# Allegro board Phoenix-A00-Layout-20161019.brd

Outline 244 x 258.83 mm; copper layers: TOP, L2_VCC, L3_GND, BOTTOM. Coordinates in mm from the lower left corner of the outline.
Outline path: 7.91,2.79 7.91,0 72.04,0 72.04,2.79 ; 125,10.37 125,10.13 ; 0,254.83 arc(1.17,257.66) 4,258.83 240,258.83 arc(242.83,257.66) 244,254.83 244,28.83 arc(242.83,26) 240,24.83 236,24.83 arc(235.29,24.53) 235,23.83 235,8.83 arc(234.41,7.41) 233,6.83 220.5,6.83 arc(219.79,7.12) 219.5,7.83 219.5,8.63 arc(219.21,9.33) 218.5,9.63 207.5,9.63 arc(206.79,9.33) 206.5,8.63 206.5,3.43 arc(205.91,2.01) 204.5,1.43 129,1.43 arc(126.17,2.6) 125,5.43 125,23.83 arc(124.71,24.53) 124,24.83 4,24.83 arc(1.17,26) 0,28.83 0,254.83

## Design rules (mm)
net group AUX_N: nets AUX_N EDP_AUX_DN_C
net group AUX_P: nets AUX_P EDP_AUX_DP_C
net group BRG_RXN: nets BRG_RXN PCH_HSON6
net group BRG_RXP: nets BRG_RXP PCH_HSOP6
net group BRG_TXN: nets BRG_TXN PCH_HSIN6
net group BRG_TXP: nets BRG_TXP PCH_HSIP6
net group BT_USB2_N6: nets BT_USB2_N6 U_USB6N_R
net group BT_USB2_N8: nets BT_USB2_N8 U_USB8N_R
net group BT_USB2_P6: nets BT_USB2_P6 U_USB6P_R
net group BT_USB2_P8: nets BT_USB2_P8 U_USB8P_R
net group CIIC_CLK: nets CIIC_SCL CIIC_SDA
net group CK_PE_100M_DMI: nets CK_PE_100M_DMI CK_PE_100M_DMI#
net group CLK_DEVICE_85OHM_4/4/15/20: nets CLKOUT_PCIE2 CLKOUT_PCIE2#
net group CLK_XTAL_24M_50OHM_4/15/20: nets XTAL_24M_IN XTAL_24M_OUT
net group CLKOUT_PCIE3: nets CLKOUT_PCIE3 N120560030
net group CLKOUT_PCIE3#: nets CLKOUT_PCIE3# N120560027
net group DMI_CPU_PCH_RXP2: nets DMI_CPU_PCH_RXN2 DMI_CPU_PCH_RXP2
net group DMI_PCH_CPU_RXP0: nets DMI_PCH_CPU_RXN0 DMI_PCH_CPU_RXP0
net group DMI_PCH_CPU_RXP2: nets DMI_PCH_CPU_RXN2 DMI_PCH_CPU_RXP2
net group EDP_LANE_DN2_C: nets EDP_LANE_DN2_C LANE0_N
net group EDP_LANE_DN3_C: nets EDP_LANE_DN3_C LANE1_N
net group EDP_LANE_DP2_C: nets EDP_LANE_DP2_C LANE0_P
net group EDP_LANE_DP3_C: nets EDP_LANE_DP3_C LANE1_P
net group EXP_A_TXN_0_C: nets EXP_A_TXN_0_C X_EXP_A_TX_C_DN0
net group EXP_A_TXN_1_C: nets EXP_A_TXN_1_C X_EXP_A_TX_C_DN1
net group EXP_A_TXN_2_C: nets EXP_A_TXN_2_C X_EXP_A_TX_C_DN2
net group EXP_A_TXN_3_C: nets EXP_A_TXN_3_C X_EXP_A_TX_C_DN3
net group EXP_A_TXN_4_C: nets EXP_A_TXN_4_C X_EXP_A_TX_C_DN4
net group EXP_A_TXN_5_C: nets EXP_A_TXN_5_C X_EXP_A_TX_C_DN5
net group EXP_A_TXN_6_C: nets EXP_A_TXN_6_C X_EXP_A_TX_C_DN6
net group EXP_A_TXN_7_C: nets EXP_A_TXN_7_C X_EXP_A_TX_C_DN7
net group EXP_A_TXN_8_C: nets EXP_A_TXN_8_C X_EXP_A_TX_C_DN8
net group EXP_A_TXN_9_C: nets EXP_A_TXN_9_C X_EXP_A_TX_C_DN9
net group EXP_A_TXN_10_C: nets EXP_A_TXN_10_C X_EXP_A_TX_C_DN10
net group EXP_A_TXN_11_C: nets EXP_A_TXN_11_C X_EXP_A_TX_C_DN11
net group EXP_A_TXN_12_C: nets EXP_A_TXN_12_C X_EXP_A_TX_C_DN12
net group EXP_A_TXN_13_C: nets EXP_A_TXN_13_C X_EXP_A_TX_C_DN13
net group EXP_A_TXN_14_C: nets EXP_A_TXN_14_C X_EXP_A_TX_C_DN14
net group EXP_A_TXN_15_C: nets EXP_A_TXN_15_C X_EXP_A_TX_C_DN15
net group EXP_A_TXP_0_C: nets EXP_A_TXP_0_C X_EXP_A_TX_C_DP0
net group EXP_A_TXP_1_C: nets EXP_A_TXP_1_C X_EXP_A_TX_C_DP1
net group EXP_A_TXP_2_C: nets EXP_A_TXP_2_C X_EXP_A_TX_C_DP2
net group EXP_A_TXP_3_C: nets EXP_A_TXP_3_C X_EXP_A_TX_C_DP3
net group EXP_A_TXP_4_C: nets EXP_A_TXP_4_C X_EXP_A_TX_C_DP4
net group EXP_A_TXP_5_C: nets EXP_A_TXP_5_C X_EXP_A_TX_C_DP5
net group EXP_A_TXP_6_C: nets EXP_A_TXP_6_C X_EXP_A_TX_C_DP6
net group EXP_A_TXP_7_C: nets EXP_A_TXP_7_C X_EXP_A_TX_C_DP7
net group EXP_A_TXP_8_C: nets EXP_A_TXP_8_C X_EXP_A_TX_C_DP8
net group EXP_A_TXP_9_C: nets EXP_A_TXP_9_C X_EXP_A_TX_C_DP9
net group EXP_A_TXP_10_C: nets EXP_A_TXP_10_C X_EXP_A_TX_C_DP10
net group EXP_A_TXP_11_C: nets EXP_A_TXP_11_C X_EXP_A_TX_C_DP11
net group EXP_A_TXP_12_C: nets EXP_A_TXP_12_C X_EXP_A_TX_C_DP12
net group EXP_A_TXP_13_C: nets EXP_A_TXP_13_C X_EXP_A_TX_C_DP13
net group EXP_A_TXP_14_C: nets EXP_A_TXP_14_C X_EXP_A_TX_C_DP14
net group EXP_A_TXP_15_C: nets EXP_A_TXP_15_C X_EXP_A_TX_C_DP15
net group F_USB2_N9: nets F_USB2_N9 USB_N9G_R
net group F_USB2_N10: nets F_USB2_N10 USB_N10G_R
net group F_USB2_P9: nets F_USB2_P9 USB_P9G_R
net group F_USB2_P10: nets F_USB2_P10 USB_P10G_R
net group F_USB3_N1: nets F_USB3_N1 U_USB1N_R
net group F_USB3_N2: nets F_USB3_N2 U_USB2N_R
net group F_USB3_P1: nets F_USB3_P1 U_USB1P_R
net group F_USB3_P2: nets F_USB3_P2 U_USB2P_R
net group FAN_PWM_4/12: nets O_CHAFAN_PWM O_CPUFAN_PWM
net group M2_SATA_RXN3_C: nets M2_SATA_RXN3_C SATA_RXN3
net group M2_SATA_RXP3_C: nets M2_SATA_RXP3_C SATA_RXP3
net group M2_SATA_TXN3_C: nets M2_SATA_TXN3_C SATA_TXN3
net group M2_SATA_TXP3_C: nets M2_SATA_TXP3_C SATA_TXP3
net group M_A_CK_D0: nets M_A_CK_DN0 M_A_CK_DP0
net group M_A_CK_D1: nets M_A_CK_DN1 M_A_CK_DP1
net group M_B_CK_D0: nets M_B_CK_DN0 M_B_CK_DP0
net group M_B_CK_D1: nets M_B_CK_DN1 M_B_CK_DP1
net group M_DQSA1: nets M_DQSA1 M_DQSA#1
net group M_DQSA2: nets M_DQSA2 M_DQSA#2
net group M_DQSA3: nets M_DQSA3 M_DQSA#3
net group M_DQSA4: nets M_DQSA4 M_DQSA#4
net group M_DQSA5: nets M_DQSA5 M_DQSA#5
net group M_DQSA6: nets M_DQSA6 M_DQSA#6
net group M_DQSB0: nets M_DQSB0 M_DQSB#0
net group M_DQSB1: nets M_DQSB1 M_DQSB#1
net group M_DQSB2: nets M_DQSB2 M_DQSB#2
net group M_DQSB3: nets M_DQSB3 M_DQSB#3
net group M_DQSB4: nets M_DQSB4 M_DQSB#4
net group M_DQSB5: nets M_DQSB5 M_DQSB#5
net group M_DQSB6: nets M_DQSB6 M_DQSB#6
net group M_DQSB7: nets M_DQSB7 M_DQSB#7
net group NIC_USB2_N4: nets NIC_USB2_N4 U_USB4N_R
net group NIC_USB2_N5: nets NIC_USB2_N5 U_USB5N_R
net group NIC_USB2_P4: nets NIC_USB2_P4 U_USB4P_R
net group NIC_USB2_P5: nets NIC_USB2_P5 U_USB5P_R
net group PCH_HSIN5: nets PCH_HSIN5 PCH_HSON5_C
net group PCH_HSIN5_C: nets PCH_HSIN5_C PCH_HSON5
net group PCH_HSIP5: nets PCH_HSIP5 PCH_HSOP5_C
net group PCH_HSIP5_C: nets PCH_HSIP5_C PCH_HSOP5
net group PCH_HSON7: nets PCH_HSON7 PCH_HSON7_C
net group PCH_HSOP7: nets PCH_HSOP7 PCH_HSOP7_C
net group PCIE_RCOMP: nets PCH_PCIE_RCOMP PCIE_RCOMP_R
net group R_USB3_N3: nets R_USB3_N3 U_USB3N_R
net group R_USB3_N7: nets R_USB3_N7 U_USB7N_R
net group R_USB3_P3: nets R_USB3_P3 U_USB3P_R
net group R_USB3_P7: nets R_USB3_P7 U_USB7P_R
net group RTC_4/15: nets ICH_RTCX1 ICH_RTCX2
net group SATA_RXN0: nets SATA_RXN0 SATA_RXN0_C
net group SATA_RXN1: nets SATA_RXN1 SATA_RXN1_C
net group SATA_RXN2: nets SATA_RXN2 SATA_RXN2_C
net group SATA_RXP0: nets SATA_RXP0 SATA_RXP0_C
net group SATA_RXP1: nets SATA_RXP1 SATA_RXP1_C
net group SATA_RXP2: nets SATA_RXP2 SATA_RXP2_C
net group SATA_TXN0: nets SATA_TXN0 SATA_TXN0_C
net group SATA_TXN1: nets SATA_TXN1 SATA_TXN1_C
net group SATA_TXN2: nets SATA_TXN2 SATA_TXN2_C
net group SATA_TXP0: nets SATA_TXP0 SATA_TXP0_C
net group SATA_TXP1: nets SATA_TXP1 SATA_TXP1_C
net group SATA_TXP2: nets SATA_TXP2 SATA_TXP2_C
net group USB3_RXDN1: nets USB3_RXDN1 USB3_RXDP1
net group USB3_TX1_PCH_DN_C: nets USB3_TX1_PCH_DN_C USB3_TXDN1
net group USB3_TX1_PCH_DP_C: nets USB3_TX1_PCH_DP_C USB3_TXDP1
net group USB3_TX2_PCH_DN_C: nets USB3_TX2_PCH_DN_C USB3_TXDN2
net group USB3_TX2_PCH_DP_C: nets USB3_TX2_PCH_DP_C USB3_TXDP2
net group USB3_TX3_PCH_DN_C: nets USB3_TX3_PCH_DN_C USB3_TXDN3
net group USB3_TX3_PCH_DP_C: nets USB3_TX3_PCH_DP_C USB3_TXDP3
net group USB3_TX4_PCH_DN_C: nets USB3_TX4_PCH_DN_C USB3_TXDN4
net group USB3_TX4_PCH_DP_C: nets USB3_TX4_PCH_DP_C USB3_TXDP4
net group ASYNCHRONOUS_50OHM_4/12: nets +DDR_PGOOD +VCCST_PWRGD APU_RST CPU_PCH_TRIGGER_OUT CPU_PCH_TRIGGER_OUT_R H_BPM#0 H_BPM#1 H_CATERR# H_PWRGOOD H_PWRGOOD_R H_THERMTRIP# PCH_CPU_TRIGGER_IN PCH_CPU_TRIGGER_IN_R PCH_ITP_PMODE PLTRST_IN_CPU# PMDOWN PMDOWN_CPU PMSYNC# PMSYNC#_R SIO_GP016 THERMTRIP#_PCH TP_BPM#2 TP_BPM#3 VCCST_PWRGD_1V VR_HOT VR_HOT_1V VRM_ALERT#_R VRM_SCLK_R VRM_SDIO_R XDP_CPU_HOOK6 XDP_CPU_HOOK6_R
net group AUDIO_10/10: nets A_HPOUT-L_R A_HPOUT-R_R A_JD1 A_JD2 A_LDO1_C A_LINE1-L_C A_LINE1-R_C A_LINE2_L_C A_LINE2_R_C A_MIC_C A_VREF AVDD2 DEPOP_LEFT DEPOP_LEFT_F DEPOP_RIGHT DEPOP_RIGHT_F HPOUT-JD HPOUT-L HPOUT-R LDO2_C LINE1-L LINE1-L_J LINE1-R LINE1-R_J LINE1-VREFO-L LINE1-VREFO-R LINE2-JD LINE2-L LINE2-R MIC2-VREFO
net group CLK_50OHM_4/15/20: nets CLKOUT_PCI0 LD_SIO_24M_CLOCKI_R PCH_24M_PCICLK SIO_24M_CLOCKI SIO_24M_CLOCKI_LPC SIO_24M_PCICLK
net group CLK_SRCCLKRQ_REQUEST_50OHM_4/15/20: nets CLK_REQ2_LAN_N CLKREQB EXP_A_PRSNT2# PCH_M2_SSD_CLKREQ_N TPM_TCM_CS V_GPI_VGA_CBL_DET# VGA_V_GPI_VGA_CBL_DET#_R
net group CRITICAL_50OHM_4/15: nets APS_PIN11 APS_PIN13 F_TP_XDP_RST FP_RST# GPP_A0 KBRST# N120811996 PCH_DPWROK PCH_DPWROK_C PCH_RSMRST# PCH_WAKE# PLTRST PLTRST_N PWRBTN_OUT# PWRBTN_OUT#_C PWRGD_140MS PWRGD_140MS_R SIO_GP026 SIO_RSMRST# TPM_RST_N VCORE_PG VCORE_PG_R WAKE#_L X16_X_RST_SLOT_PEG#_R X_PLTRST_PCIE_SLOT# X_RST_SLOT_PEG# X_RST_SLOT_PEG#_R XDP_FP_RST# XDP_PWRBTN_OUT# XDP_RSMRST#
net group DDR_A_ALERT_4/8: nets M_A_ALERT_N
net group DDR_A_CMD_35OHM_O8P5/6P5: nets M_A_ACT_N M_A_BA0 M_A_BA1 M_A_BA2 M_A_BG1 M_A_MA0 M_A_MA1 M_A_MA2 M_A_MA3 M_A_MA4 M_A_MA5 M_A_MA6 M_A_MA7 M_A_MA8 M_A_MA9 M_A_MA10 M_A_MA11 M_A_MA12 M_A_MA13 M_A_MA14 M_A_MA15 M_A_MA16 M_A_PAR
net group DDR_A_CTL_DIMM1_40OHM_O6P5/9P5: nets M_A_CKE0 M_A_CKE1 M_A_CS_N0 M_A_CS_N1 M_A_ODT0 M_A_ODT1
net group DDR_A_DATA0_40OHM_O6P5/18P5: nets M_DA0 M_DA1 M_DA2 M_DA3 M_DA4 M_DA5 M_DA6 M_DA7
net group DDR_A_DATA1_40OHM_O6P5/18P5: nets M_DA8 M_DA9 M_DA10 M_DA11 M_DA12 M_DA13 M_DA14 M_DA15
net group DDR_A_DATA2_40OHM_O6P5/18P5: nets M_DA16 M_DA17 M_DA18 M_DA19 M_DA20 M_DA21 M_DA22 M_DA23
net group DDR_A_DATA3_40OHM_O6P5/18P5: nets M_DA24 M_DA25 M_DA26 M_DA27 M_DA28 M_DA29 M_DA30 M_DA31
net group DDR_A_DATA4_40OHM_O6P5/18P5: nets M_DA32 M_DA33 M_DA34 M_DA35 M_DA36 M_DA37 M_DA38 M_DA39
net group DDR_A_DATA5_40OHM_O6P5/18P5: nets M_DA40 M_DA41 M_DA42 M_DA43 M_DA44 M_DA45 M_DA46 M_DA47
net group DDR_A_DATA6_40OHM_O6P5/18P5: nets M_DA48 M_DA49 M_DA50 M_DA51 M_DA52 M_DA53 M_DA54 M_DA55
net group DDR_A_DATA7_40OHM_O6P5/18P5: nets M_DA56 M_DA57 M_DA58 M_DA59 M_DA60 M_DA61 M_DA62 M_DA63
net group DDR_B_ALERT_4/8P5: nets M_B_ALERT_N
net group DDR_B_CMD_35OHM_I7/10P5: nets M_B_ACT_N M_B_BA0 M_B_BA1 M_B_BA2 M_B_BG1 M_B_MA0 M_B_MA1 M_B_MA2 M_B_MA3 M_B_MA4 M_B_MA5 M_B_MA6 M_B_MA7 M_B_MA8 M_B_MA9 M_B_MA10 M_B_MA11 M_B_MA12 M_B_MA13 M_B_MA14 M_B_MA15 M_B_MA16 M_B_PAR
net group DDR_B_CTL_DIMM2_40OHM_I5P5/14/14P25: nets M_B_CKE0 M_B_CKE1 M_B_CS_N0 M_B_CS_N1 M_B_ODT0 M_B_ODT1
net group DDR_B_DATA0_5P5/20: nets M_DB0 M_DB1 M_DB2 M_DB3 M_DB4 M_DB5 M_DB6 M_DB7
net group DDR_B_DATA1_5P5/20: nets M_DB8 M_DB9 M_DB10 M_DB11 M_DB12 M_DB13 M_DB14 M_DB15
net group DDR_B_DATA2_5P5/20: nets M_DB16 M_DB17 M_DB18 M_DB19 M_DB20 M_DB21 M_DB22 M_DB23
net group DDR_B_DATA3_5P5/20: nets M_DB24 M_DB25 M_DB26 M_DB27 M_DB28 M_DB29 M_DB30 M_DB31
net group DDR_B_DATA4_5P5/20: nets M_DB32 M_DB33 M_DB34 M_DB35 M_DB36 M_DB37 M_DB38 M_DB39
net group DDR_B_DATA5_5P5/20: nets M_DB40 M_DB41 M_DB42 M_DB43 M_DB44 M_DB45 M_DB46 M_DB47
net group DDR_B_DATA6_5P5/20: nets M_DB48 M_DB49 M_DB50 M_DB51 M_DB52 M_DB53 M_DB54 M_DB55
net group DDR_B_DATA7_5P5/20: nets M_DB56 M_DB57 M_DB58 M_DB59 M_DB60 M_DB61 M_DB62 M_DB63
net group DDR_RST_O4/8_I4/8P5: nets DDR4_DRAMRST# M_AB_RESET_N M_AB_RESET_N_R
net group DDR_VREF_O10/12: nets DIMM_DQ_CPU_VREF_A DIMMA_VREF_RC DIMMB_VREF_RC M_A_VREF M_B_VREF M_CA_VREF M_CA_VREF_RC M_DQ_VREF M_DQ_VREF_RC
net group DISPA_TBD: nets PCH_DISPA_BCLK PCH_DISPA_BCLK_R PCH_DISPA_SDI PCH_DISPA_SDI_R PCH_DISPA_SDO PCH_DISPA_SDO_R
net group DP_DATA/CLK_50OHM_4/12/15: nets HDMI_D41_PIN1 HDMI_D41_PIN2 HDMI_Q99_S HDMI_Q104_S
net group DPB_LANE_DN0_C: nets V_HDMI_TX2_DN
net group DPB_LANE_DN1_C: nets V_HDMI_TX1_DN
net group DPB_LANE_DN2_C: nets V_HDMI_TX0_DN
net group DPB_LANE_DN3_C: nets V_HDMI_CLK_DN
net group DPB_LANE_DP0_C: nets V_HDMI_TX2_DP
net group DPB_LANE_DP1_C: nets V_HDMI_TX1_DP
net group DPB_LANE_DP2_C: nets V_HDMI_TX0_DP
net group DPB_LANE_DP3_C: nets V_HDMI_CLK_DP
net group EDP_COMP_5/25: nets EDP_RCOMP
net group ESPI_50OHM_4/5: nets LAD2_SPIIRQ LPC_AD0 LPC_AD0_DEBUG LPC_AD0_TCM LPC_AD1 LPC_AD1_DEBUG LPC_AD1_TCM LPC_AD2 LPC_AD2_DEBUG LPC_AD2_TCM LPC_AD3 LPC_AD3_DEBUG LPC_AD3_TCM LPC_FRAME# LPC_FRAME#_DEBUG LPC_FRAME#_TCM PCH_LPC_AD0 PCH_LPC_AD1 PCH_LPC_AD2 PCH_LPC_AD3 PCH_LPC_FRAME# PLTRST#_SD_LPC PLTRST#_SD_LPC_DEBUG PLTRST#_SD_LPC_TCM SER_IRQ SUS_STAT_N TPM_SPIIRQ
net group HDA_TBD: nets A_QA3_G AUD_BITCLK AUD_BITCLK_R AUD_LINK_RESET# AUD_LINK_SDI0 AUD_LINK_SDIO_R AUD_SYNC FLASH_OVERRIDE# PCH_HDBCLK PCH_HDRST# PCH_HDSDO PCH_HDSYNC RSDATA_OUT
net group I2S_50OHM_4/10: nets O_AUD_PCSPKR_DET#
net group LAN_XTAL_4/15: nets XTAL_IN XTAL_OUT XTAL_OUT_R
net group OTHERS: nets 1P0V_PCH_EN 1P0V_PCH_FB 1P0V_PCH_FB_R 1P0V_PCH_PG 1P0V_PCH_SS 1P0V_PCH_TON 1P0V_PCH_VCCDSW 1P0V_PCH_VCCF24_FB_R 1P0V_PCH_VIN 1P0V_VCCAMPHYPLL_FB_R 1P0V_VCCAPLL_FB_R 3V_5V_PWROK 5V_DUAL_USB_EN_M 5V_SMART_USB_EN +1P0V_PCH_SN +1P0V_VCCST +1P2V_VDDQ_CS +1P2V_VDDQ_EN +1P2V_VDDQ_FB +1P2V_VDDQ_FB_R +1P2V_VDDQ_RF +1P2V_VDDQ_VCC +1P5V_VA +1P5V_VA_ADJ +3P3V_LPS_LDO +3P3V_PCIAUX +3P3V_SB_CS +3P3V_SB_FB +3P3V_SB_FB_R +3V_5V_EN +3V_5V_EN_3V +3V_5V_EN_3V_R +3V_5V_EN_5V +3V_5V_EN_R +3V_BATT +3V_VA +5V/3P3V_VIN +5V_3P3V_PG +5V_DDC +5V_HDMI +5V_PS2 +5V_SMART_USB +5V_USB_EN_L +5VAUX_CS +5VAUX_EN +5VAUX_FB +5VAUX_FB_R +5VAUX_LPS_LDO +5VAUX_VCLK +12V_SB +VCCGT +VCCIO_COMP_RC +VCCIO_DRV +VCCIO_DRV_R +VCCIO_FB +VCCIO_FB_R +VCCIO_FB_RC +VCCIO_FB_SENSE +VCCIO_SS +VCCIO_VCC +VCCRTC_SIO +VCCSA_CS +VCCSA_FB +VCCSA_FB_R +VCCSA_FB_VSS +VCCSA_RF +VCCSA_SN_20 +VCCSA_VCC_20 +VCCST_PWRGD_R +VCORE +VPP +VPP_BST +VPP_BST_RC +VPP_EN +VPP_FB +VPP_FB_R +VPP_FB_RC +VPP_LSN +VPP_PG +VPP_PVCC +VPP_VIN +VTT -12V -12V_COMP -12V_SWC -12V_SWE -12V_TCAP A_CBN A_CBP A_CPVEE A_EAPD_R A_FP_PRES# A_GND_C A_LDO3_C A_PCBEEP_C A_PVDD1 A_QA4_G A_SET A_SPEAKER_C A_SPKR_C A_VD33_STB APS_PIN1 APS_PIN2 APS_PIN3 APS_PIN4 APS_PIN5 APS_PIN6 AVCC33 B_ATX_PWROK BATT1 BATT_R_2 BRG_CLK_F3 BRG_REF0_PCIE BRG_REF1_PCIE BRG_REF01_PCIE_R BRG_TP_L10 BRG_TP_M11 BRG_TP_N12 BRG_VDD_15_COMB BRG_VDD_33_COMB BRG_VDD_33_COMBIO C_CLK_OUT0 C_CLK_OUT1 C_PCI_SL1 C_PCI_SL2 CFG0 CFG1 CFG2 CFG3 CFG4 CFG5 CFG6 CFG7 CFG8 CFG9 CFG10 CFG11 CFG12 CFG13 CFG14 CFG15 CFG16 CFG17 CFG18 CFG19 CFG_RCOMP CKBCLK CKBDATA CL_CLK_WLAN CL_DATA_WLAN CL_RST_WLAN# CL_SENCE# CLKRUN_EN CMCLR_2 CMSCLK CMSDATA CPU_FAN_+12V CPU_PRDY_N CPU_PREQ_N CPU_SELECT# D1_1 DDR_VTT_CNTL DP_HPD DPB_HPD_R DVCC_1P5V DVCC_1P5V_ADJ EAPD EAPD_R EDP_HPD_DDPE EDP_HPD_R ESPI_ALERT0 EVENT_A_R EVENT_B_R EXTARB_EN F_PCH_JTAG_TDI F_PCH_JTAG_TDO F_PCH_JTAG_TMS F_SPI_VCC FAN_CPU_PIN1 FAN_CPU_PWM FPNL_SATA_LED#_R GPIO0 GPIO2 GPIO4 GPIO_PEG SLOT_RESET GPP_A8 GPP_A13 GPP_B14 GPP_F17 GPP_F18 H_SKTOCC# H_TCK H_TDI H_TDO H_TMS H_TRST# H_TRST#_R HDMI_HPD HDMID_FET_SINK HS_DET# ISOLATEB JTAG_TCK JTAG_TRST# K_AD0 K_AD1 K_AD2 K_AD3 K_AD4 K_AD5 K_AD6 K_AD7 K_AD8 K_AD9 K_AD10 K_AD11 K_AD12 K_AD13 K_AD14 K_AD15 K_AD16 K_AD17 K_AD18 K_AD18_R K_AD19 K_AD20 K_AD21 K_AD22 K_AD23 K_AD24 K_AD25 K_AD26 K_AD27 K_AD28 K_AD29 K_AD30 K_AD31 K_C/BE#0 K_C/BE#1 K_C/BE#2 K_C/BE#3 K_DEVSEL# K_FRAME# K_GNT#0 K_GNT#1 K_INTA# K_INTB# K_INTC# K_INTD# K_IRDY# K_LOCK# K_PAR K_PCI_M66EN K_PCI_PME# K_PCIRST#_N K_PCIRST#_SLOT K_PERR# K_PME# K_REQ#0 K_REQ#1 K_SERR# K_STOP# K_TCK K_TCK1 K_TDI K_TDI1 K_TMS K_TMS1 K_TRDY# K_TRST K_TRST1 KBDCLK KBDDATA L_ACTLEDN L_ACTLEDN_R L_LINK100# L_LINK100#_R L_LINK1000# L_LINK1000#_R LAN_DISABLE# LAN_DISABLE#_R LAN_QL5_B LAN_QL5_C LAN_QL6_B LAN_QL7_G LAN_WAKE# LD_FP_RST#_R LD_LPC_DEBUG_PIN2 LD_LPC_DEBUG_PIN6 LDO_EN LED_M2_SSD_ACT_N LED_YELLOW_R M2_DEVSLP M2_PE_WAKE# M2_Q1_C M2_Q1A_B M2_Q2_B M.2_PEDET M.2_SSD_PEDET MSCLK MSDATA N120812085 N120812204 N120812265 N120812340 N120964019 N121283078 N121341151 N121341154 N121428079 N121488357 N121515008 N121515022 N121515024 N121515291 N121515335 O_+12VCOM O_-12VCOM O_A20GATE O_AUD_PCSPKR_DET#_SIO O_CPUFAN_PWM_R O_CTS1# O_CTS1#_R O_DCD1# O_DCD1#_R O_DSR1# O_DSR1#_R O_DTR1# O_DTR1#_R O_FIO_SATA_LED# O_FP_CBL_DET#_SIO O_GREEN# O_GREEN#_CTL O_GREEN#_R O_MB_REG_PG O_MB_REG_PG_R O_MEM_REG_PG O_MEM_REG_PG_R O_PCIAUX_CTRL O_PCIAUX_CTRL_R O_PWR2_PRSNT_R O_QO11_2 O_QO11_5 O_RI1# O_RI1#_R O_RTS1# O_RTS1#_R O_RXD1 O_RXD1_R O_SEN_CHAFAN O_SEN_CPUFAN O_SEN_CPUFAN_R O_SPEAKER O_SUS_3V_F_ON O_SUS_3V_ON O_SUS_3VON O_SUS_5VON O_TRST# O_TXD1 O_TXD1_R O_TXD1_R_C O_V5_ALW_MON O_V_IN O_YELLOW# O_YELLOW#_CTL O_YELLOW#_R OQ14_C PCH_AUD_MUTE PCH_FVS PCH_GPD0 PCH_GPD1 PCH_GPD4 PCH_GPD5 PCH_GPD6 PCH_JTAG_TCK PCH_OC#_0 PCH_OC#_1 PCH_OC#_2 PCH_OC#_3 PCH_OC#_4 PCH_OC#_5 PCH_PRDY_N PCH_PREQ_N PCH_STRAP_BBS PCH_STRAP_ESPI_EN PCH_STRAP_EXI_N PCH_STRAP_GPP_B18 PCH_STRAP_GPP_H12 PCH_STRAP_TLS PCI_CLKREQ# PCI_FBCLK PCI_REQ2# PCI_REQ3# PCI_REQ4# PCI_REQ5# PCIAUX_GATE_R PCIE_SLOT2_PRSNT_N PCIR PCLK66_SEL PD_USB2_VBUSSENSE PDB PECI_REQUEST POL1_SDA POL2_SCL PQ7_G PQ7_G_R PQ9_G PQ16_D1 PQ18A_BASE PQ18B_BASE PQ19_D1 PQ21_G1 PQ21B_D1 PQ24B_D PQ24B_G PQ42A_D1 PQ42A_G1 PQ47_C PQ47_G PQ49B_GATE PQ53_G1 PQ54_G PQ55_G PQ55B_D PQ57A_D1 PQ57B_G2 PQ71_D1 PQ79_C PQ79_G PU21_Y PV_RTCEXT QS10_B QS10_E REFCLK_SEL REGOUT RGB_IMPEDANCE RING2 RING2_J RTK_RSET_R S_GPI_BRD_REV0 S_GPI_BRD_REV1 S_MFG_MODE_OR S_PCIAUX_GATE S_PME# S_PSWD_CLR S_SLP_S5#_SIO S_USB3_HDR_DET# SATA_LED# SATAGP0 SATAGP0_R SATAGP1 SATAGP2 SATAGP3 SATAGP4 SATAGP5 SATAGP5_R SATAGP6 SATAGP6_R SATAGP7 SD4_WAKE SER_SENCE# SERIRQ SERVICE_MODE_1 SIO_24M_TCM SIO_CAP1 SIO_CLOCKI SIO_GP004 SIO_GP010 SIO_GP011 SIO_GP071 SIO_PCIAUX_G SIO_PECI_R SIO_PWRGD SIO_QO1A_B SIO_QO1B_B SIO_QO2A_B SIO_QO2B_B SIO_QO3A_B SIO_QO3B_B SIO_QO4A_B SIO_QO4B_B SIO_QO5A_B SIO_QO5B_B SIO_SLP_S4#_R SIO_SLP_SUS SIO_SLP_WLAN_N_R SLEEVE SLEEVE_J SLP_A# SLP_S0_N SLP_S3# SLP_S4# SLP_S5# SLP_SUS# SLP_SUS#_PCH SLP_SUS_FET_R SLP_WLAN_N SPI_VDD1 SPI_VDD3 SPKR SSD_SATA_DEVSLP3 SUS_PWR_ACK# SUS_WARN# SUSCLK_PCH SUSCLK_SIO SW_TPM SYS_FAN_+12V SYSTEM_FAN22 SYSTEM_FAN23 TCM_SIO_24M_TCM_R TCM_SIO_CLOCKI_R TCM_UF3_PIN2 TMIN_SHIFT TP_AJ24 TP_AK21 TP_AK22 TP_APU_RSVD_AC37 TP_APU_RSVD_AU9 TP_APU_RSVD_AU10 TP_APU_RSVD_AU39 TP_APU_RSVD_AU40 TP_APU_RSVD_AV39 TP_APU_RSVD_AW38 TP_APU_RSVD_B39 TP_APU_RSVD_C40 TP_APU_RSVD_D15 TP_APU_RSVD_J11 TP_APU_RSVD_J13 TP_APU_RSVD_J14 TP_APU_RSVD_J15 TP_APU_RSVD_J17 TP_APU_RSVD_J19 TP_APU_RSVD_K10 TP_APU_RSVD_K11 TP_APU_RSVD_K12 TP_APU_RSVD_K13 TP_APU_RSVD_L10 TP_APU_RSVD_L12 TP_APU_RSVD_TP_AV1 TP_APU_RSVD_TP_AW2 TP_APU_RSVD_TP_H11 TP_APU_RSVD_TP_H12 TP_APU_RSVD_TP_J7 TP_APU_RSVD_TP_J8 TP_APU_RSVD_TP_K8 TP_APU_RSVD_TP_L8 TP_APU_ZVM# TP_EDP_DISP TP_F36 TP_F37 TP_GPP_D4_ISH_I2C2_SDA TP_GPP_D14_ISH_UART0_TXD TP_GPP_D18_DMIC_DATA1 TP_GPP_D19_DMIC_CLK0 TP_GPP_H15_SML3ALERT_N TP_GPP_H18_SML4ALERT_N TP_PCH_B19 TP_PCH_B20 TP_PCH_C19 TP_PCH_C20 TP_PCH_E17 TP_PCH_G17 TP_PCH_K17 TP_PCH_L17 TP_PCH_RSVD0 TP_PCH_RSVD1 TP_PCH_RSVD2 TP_PCH_RSVD3 TP_PCH_RSVD4 TP_PCH_RSVD5 TP_PCH_RSVD6 TP_PCH_RSVD7 TP_PCH_RSVD8 TP_PCH_RSVD9 TP_PCH_RSVD10 TP_PCH_RSVD11 TP_PCH_RSVD12 TP_PCH_RSVD13 TP_PCH_RSVD14 TP_PCH_RSVD15 TP_PCH_RSVD16 TP_PCH_RSVD17 TP_PCH_RSVD18 TP_PCH_TP4 TP_PCH_TP5 TP_SIO_GP054 TPM_BADD TPM_PP TPM_QF1_G TPM_SERIRQ TPM_VDD2 UEFI_S USB2_ID USBPWR0_F_50 USBPWR1_F_50 USBPWR4_F_50 USBPWR5_F_50 V_BLUE_R V_GREEN_R V_HSYNC_5V_R V_RED_R V_VSYNC_5V_R VCC_AUD VCC_OBS_AB VCC_OBS_CD VCC_OBS_R VCC_OPC_R VCCEOPIO_R VCCGT_HSN_1 VCCGT_HSN_2 VCCGTX2_L31 VCCHDA_BA15 VCCIO_EN VCCIO_PG VCCIO_SENSE VCCK_V12 VCCOPC_R VCCPGPPA VCCPGPPCD_BA45 VCCPLL_OC_R VCCPRIM_AL22 VCCPRIM_BE3 VCCSA_SENSE VCCSOKET VCCSPI VCORE_EN VCORE_EN_FREQUENCE VCORE_HSN_1 VCORE_HSN_2 VCORE_HSN_3 VCT VDD10 VDD_DAC_33 VDDA_1P5V VDDA_3P3V VDDQ_SN VDDQ_VTT_REFEN VGA_5V_DDC_R VGA_BLUE_P VGA_GREEN_P VGA_HSYNC VGA_PRX_PIN28 VGA_RED_P VGA_RGB_CV VGA_SCL VGA_SDA VGA_VSYNC VGAPWR_F_20 VGT_VCC1_20 VGT_VCC2_20 VISACH1_D2_PCH_GPP_E_5 VISACH1_D2_PCH_GPP_E_6 VPP_PG VRALERT_N VREF_RC VREG_PD33 VRM_SETA1 VRM_SN1_20 VRM_SN2_20 VRM_SN3_20 VRM_VCC VRM_VCC1_20 VRM_VCC2_20 VRM_VCC3_20 VSS_AB10 VSS_AB11 VSSSAIO_SENSE VSSSOKET WAKE_SLOT1_N WAKE_SLOT_M2_N X1_TCLK X1_TDI X1_TRST X16_RST_SLOT_PEG# X16_RST_SLOT_PEG#_R X16_TCLK X16_TDI X16_TMS X16_TRST X_PCI1_ACK64#_R X_PCI1_K_AD17_R X_PCI1_REQ64#_R X_PCI1_SMBCLK_R X_PCI1_SMBDATA_R X_PCI_ACK64#_B60 X_PCI_REQ64#_A60 X_PCI_SMBCLK_R X_PCI_SMBDATA_R XDP_HOOK2 XDP_PCH_JTAGX XDP_PRESENT#_CPU
net group PECI_50OHM_4/18: nets H_PECI H_PECI_C PCH_PECI_R
net group PEG_RCOMP_5/15: nets PEGICOMP_MCP
net group PHASE_20: nets +1P2V_VDDQ_BOOT_20 +1P2V_VDDQ_BOOT_R20 +1P2V_VDDQ_LG_30 +1P2V_VDDQ_UG_20 +1P2V_VDDQ_UG_R20 +3P3V_SB_BOOT_20 +3P3V_SB_BOOTR_20 +5VAUX_BOOT_20 +5VAUX_BOOTR_20 PQ11_GATE PQ11_GATE_R PQ23_GATE VGT_BOOT1_20 VGT_BOOT1_RC_20 VGT_BOOT2_20 VGT_BOOT2_RC_20 VGT_LG1_R_30 VGT_LG2_R_30 VGT_SN1_20 VGT_SN2_20 VGT_UG1_20 VGT_UG1_R_20 VGT_UG2_20 VGT_UG2_R_20 VRM_BOOT1_20 VRM_BOOT1_RC_20 VRM_BOOT2_20 VRM_BOOT2_RC_20 VRM_BOOT3_20 VRM_BOOT3_RC_20 VRM_LG1_R_30 VRM_LG2_R_30 VRM_LG3_R_30 VRM_UG1_20 VRM_UG1_R_20 VRM_UG2_20 VRM_UG2_R_20 VRM_UG3_20 VRM_UG3_R_21
net group PHASE_25: nets 1P0V_PCH_BOOT_25 +3P3V_SB_LG_25 +3P3V_SB_PHASE_R +3P3V_SB_UG25 +3P3V_SB_UGR_25 +5VAUX_LG_25 +5VAUX_PHASE_R +5VAUX_UG_25 +5VAUX_UGR_25 +VCCSA_BOOT_25 +VCCSA_BOOT_R25 +VCCSA_HG_25 +VCCSA_HG_R_25 +VCCSA_LG_25
net group PWM_8: nets COMP_R COMPA_R CS1+_RT3607 CS1-_RT3607 CS2+_RT3607 CS2-_RT3607 CS3+_RT3607 CS3-_RT3607 CS4-_RT3607 GT1+_RT3607 GT1-_RT3607 GT2+_RT3607 GT2-_RT3607 GT3-_RT3607 GT_COMPA GT_FBA GT_VSENA IMON IMON_L IMON_R IMONA IMONA_L IMONA_R RGNDA TONSET_R TONSETA TONSETA_R TSEN TSEN_R1 TSEN_R2 TSENA TSENA_R1 TSENA_R2 VCCGT_PWM1_10 VCCGT_PWM2_10 VCCGT_SENSE VREF_R VREF_RA VRM_COMP VRM_DVD VRM_FB VRM_IBIAS VRM_PWM1_10 VRM_PWM2_10 VRM_PWM3_10 VRM_RGND VRM_SET1 VRM_SET1_R VRM_SET1_RR VRM_SET2 VRM_SET2_R VRM_SET2_RR VRM_SET3 VRM_SET3_R VRM_SET3_RR VRM_SETA1_R VRM_SETA1_RR VRM_SETA2 VRM_SETA2_R VRM_SETA2_RR VRM_TON VRM_VREF VRM_VSEN VSSGT_SENSE
net group RTCRST_4/15: nets APS_PIN9 ICH_RTCRST# O_PSON#
net group SPI_50OHM_4/5: nets CS2_LFRAM# F_SPI_HOLD# F_SPI_MISO_R F_SPI_MISO_TPM F_SPI_MOSI_PRI_SEC_FLSH_R F_SPI_MOSI_PRI_SEC_FLSH_TPM F_SPI_WP# LAD0_MISO LAD1_MOSI SPI_CS# SPI_IO2 SPI_IO3 SPI_MISO SPI_MOSI SPI_TPM_CS2# TPM_CS2_LFRAM#_R XDP_PRESENT#_R XDP_SPI_MOSI
net group SPI_CLK_50OHM_4/15: nets F_SPI_CLK_PRI_SEC_FLSH_R F_SPI_CLK_PRI_SEC_FLSH_TPM SPI_SCK TPM_CLK
net group SRTCRST#_4/15: nets SRTCRST#_ICH
net group SVID_50OHM_4/15: nets VIDALERT_# VIDSCLK VIDSOUT VRM_ALERT# VRM_SCLK VRM_SDIO
net group UART2_50OHM_4/5: nets RING#
net group USB_COMP_50OHM_4/15: nets A_USB2_COMP
net group XCLK_BIASREF_4/15/20: nets XCLK_RCOMP

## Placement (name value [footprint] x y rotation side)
APS/PETS  Header_2X7_GF_Black  [H2X7MZ]  10.19 185.8 180 top
ATX_CPU  PWR_2X2_4.2_Nature  [PWR4NWP1]  223.83 204.15 270 top
ATX_SYS  PWR_2X4_4.2_100u_Nature  [PWR_2X4_165_PEGL_WL496]  34.08 29.9 180 top
AUX_PWR1  LED_Yellow  [D0603_H31]  11.72 34.54 180 top
BATTERY  Battery Holder_H  [BAT2_200D223-1]  186.95 50.41 180 top
BH1  74LVC1G17SE-7  [SOT353_5]  29.37 116.46 270 top
BRIDGE  XIO2001ZGU  [BGA_169_472X472]  59.6 196.6 180 top
C1  1uF_X5R_6.3V  [C0402]  170.54 84.51 90 top
C2  1uF_X5R_6.3V  [C0402]  167.6 84.53 90 top
C3  1uF_X5R_6.3V  [C0402]  108.36 84.45 0 top
C5  1uF_X5R_6.3V  [C0402]  147.51 84.53 90 top
C6  100nF_X5R_10V  [C0402]  117.64 84.45 180 top
C7  100nF_X5R_10V  [C0402]  147.35 94.23 270 top
C8  100nF_X5R_10V  [C0402]  145.73 84.53 270 top
C9  100nF_X5R_10V  [C0402]  152.18 95.5 270 top
C19  100nF_X5R_10V  [C0402]  149.13 94.23 270 top
C20  4.7uF_X5R_6.3V  [C0603]  155.61 73.66 180 top
C21  100nF_X5R_6.3V  [C0402]  159.29 72.77 0 top
C22  100nF_X7R_10V  [C0402]  99.73 93.09 0 top
C23  100nF_X7R_10V  [C0402]  99.73 94.11 0 top
C24  2.2uF_X5R_6.3V  [C0402]  107.86 75.82 180 top
C25  100nF_X7R_16V  [C0402]  109.89 75.82 0 top
C48  1uF_X5R_6.3V  [C0402]  161.7 84.48 90 top
C49  1uF_X5R_6.3V  [C0402]  208.31 84.58 180 top
C50  1uF_X5R_6.3V  [C0402]  181.41 84.53 90 top
C51  1uF_X5R_6.3V  [C0402]  217.58 84.33 180 top
C52  100nF_X5R_10V  [C0402]  167.93 94.74 270 top
C53  100nF_X5R_10V  [C0402]  162.97 94.62 270 top
C54  100nF_X5R_10V  [C0402]  159.8 94.62 270 top
C55  100nF_X5R_10V  [C0402]  172.25 75.31 90 top
C56  100nF_X5R_10V  [C0402]  149.77 84.45 180 top
C57  22uF_X5R_6.3V  [C0805]  188.37 84.45 180 top
C58  22uF_X5R_6.3V  [C0805]  212.89 84.58 180 top
C59  22uF_X5R_6.3V  [C0805]  175.04 95.63 0 top
C60  22uF_X5R_6.3V  [C0805]  175.04 93.98 0 top
C61  22uF_X5R_6.3V  [C0805]  174.66 84.58 0 top
C62  4.7uF_X5R_6.3V  [C0603]  156.93 84.56 180 top
C63  100nF_X5R_6.3V  [C0402]  159.29 84.71 0 top
C64  100nF_X7R_10V  [C0402]  98.33 84.96 0 top
C65  100nF_X7R_10V  [C0402]  98.33 84.07 0 top
C66  2.2uF_X5R_6.3V  [C0402]  101.25 84.07 0 top
C67  100nF_X7R_16V  [C0402]  101.25 84.96 0 top
C68  2.2uF_X5R_6.3V  [C0402]  221.78 75.44 270 top
C69  100nF_X7R_16V  [C0402]  222.79 75.44 270 top
C70  100nF_X7R_10V  [C0402]  119.3 193.04 90 top
C71  100nF_X7R_10V  [C0402]  216.31 75.44 270 top
C72  4.7uF_X5R_6.3V  [C0603]  220.63 75.06 270 top
C73  22nF_X7R_16V  [C0402]  224.82 75.44 90 top
C74  100nF_X7R_10V  [C0402]  130.14 195.66 90 top
C75  100nF_X7R_10V  [C0402]  130.88 207.39 90 top
C228  1uF_X5R_16V  [C0603]  170.72 56.26 0 top
C379  10nF_X7R_25V  [C0402]  186.22 234.19 180 top
C383  10nF_X7R_25V  [C0402]  181.9 224.28 0 top
C386  10nF_X7R_25V  [C0402]  178.47 234.06 180 top
C409  100nF_X7R_16V  [C0402]  159.55 238.96 270 top
C410  150pF_NPO_25V  [C0402]  151.04 235.33 270 top
C411  150pF_NPO_25V  [C0402]  151.04 237.36 270 top
C412  150pF_NPO_25V  [C0402]  146.46 235.2 270 top
C413  150pF_NPO_25V  [C0402]  146.46 237.24 270 top
C414  100pF_NPO_50V  [C0402]  158.53 238.94 270 top
C415  10nF_X7R_25V  [C0402]  160.57 238.96 90 top
C531  100nF_X7R_16V  [C0402]  225.54 253.11 0 top
C558  470pF_X7R_50V  [C0402]  219.45 242.09 270 top
C766  100nF_X7R_16V  [C0402]  172.12 53.72 0 top
C1629  100pF_X7R_50V  [C0402]  31.28 118.75 270 top
C1630  1uF_X5R_6.3V  [C0402]  42.71 130.56 180 top
C1639  1uF_X5R_6.3V  [C0603]  39.78 130.81 0 top
C1640  12pF_NPO_50V  [C0402]  40.04 132.21 180 top
C1641  12pF_NPO_50V  [C0402]  40.04 133.22 180 top
C1642  27pF_NPO_50V  [C0402]  74.58 132.59 315 top
C1643  27pF_NPO_50V  [C0402]  74.46 133.99 0 top
C1644  100nF_X7R_10V  [C0402]  43.34 119.63 90 top
C1645  1uF_X5R_6.3V  [C0402]  42.32 119.63 90 top
C1646  1uF_X5R_6.3V  [C0402]  62.14 142.11 180 top
C1647  1uF_X5R_6.3V  [C0402]  40.93 121.28 180 top
C1648  100nF_X7R_10V  [C0402]  40.04 111 0 top
C1649  100nF_X7R_10V  [C0402]  40.04 110.11 0 top
C1654  47uF_X5R_6.3V  [C0805]  73.95 111.73 0 top
C1655  47uF_X5R_6.3V  [C0805]  73.95 110.08 0 top
C1656  47uF_X5R_6.3V  [C0805]  43.59 109.35 270 top
C1657  47uF_X5R_6.3V  [C0805]  41.94 109.35 270 top
C1660  22uF_X5R_6.3V  [C0805_H37]  56.68 147.57 0 top
C1661  22uF_X5R_6.3V  [C0805_H37]  56.68 145.8 0 top
C1664  22uF_X5R_6.3V  [C0805_H37]  67.85 110.11 180 top
C1665  22uF_X5R_6.3V  [C0805_H37]  67.85 108.33 180 top
C1666  1uF_X5R_6.3V  [C0402]  70.52 107.95 0 top
C1667  1uF_X5R_6.3V  [C0402]  72.14 107.57 225 top
C1668  1uF_X5R_6.3V  [C0402]  62.39 143.13 180 top
C1670  22uF_X5R_6.3V  [C0805_H37]  65.18 139.83 180 top
C1671  22uF_X5R_6.3V  [C0805_H37]  65.18 141.48 180 top
C1672  1uF_X5R_6.3V  [C0402]  64.55 138.43 180 top
C1677  22uF_X5R_6.3V  [C0805_H37]  63.41 144.53 180 top
C1678  100nF_X7R_10V  [C0402]  40.42 119.63 90 top
C1679  1uF_X5R_6.3V  [C0402]  54.64 148.97 180 top
C1681  100nF_X7R_10V  [C0402]  42.07 136.14 270 top
C1682  1uF_X5R_6.3V  [C0402]  42.32 121.79 270 top
C1683  100nF_X7R_10V  [C0402]  43.34 121.79 270 top
C1684  100nF_X7R_10V  [C0402]  44.86 106.43 90 top
C1686  100nF_X7R_10V  [C0402]  44.99 109.35 90 top
C1688  1uF_X5R_6.3V  [C0402]  40.04 109.22 180 top
C1689  100nF_X7R_10V  [C0402]  42.83 124.59 0 top
C1722  22uF_X5R_6.3V  [C0805]  102.65 98.93 180 top
C1723  100pF_NPO_50V  [C0402]  65.82 151 90 top
C1724  100pF_NPO_50V  [C0402]  10.7 79.88 90 top
C1728  1uF_X5R_6.3V  [C0402]  102.65 100.46 180 top
C1763  1uF_X5R_10V  [C0603]  27.47 131.83 180 top
C1764  100nF_X7R_16V  [C0402]  31.53 115.7 90 top
C1766  22uF_X5R_6.3V  [C0805]  131.61 84.58 0 top
C1767  22uF_X5R_6.3V  [C0805]  140.75 84.53 0 top
C1768  22uF_X5R_6.3V  [C0805]  140.75 74.68 270 top
C1769  22uF_X5R_6.3V  [C0805]  164.5 84.58 0 top
C1807  1uF_X5R_6.3V  [C0402]  62.14 141.1 180 top
C1808  1uF_X5R_6.3V  [C0402]  39.02 142.24 90 top
CA1  10uF_X5R_6.3V  [C0603]  182.79 15.7 270 top
CA2  10uF_X5R_6.3V  [C0603]  189.52 19.89 0 top
CA3  10uF_X5R_6.3V  [C0603]  191.96 19.68 270 top
CA4  10uF_X5R_6.3V  [C0603]  193.33 19.64 270 top
CA5  2.2uF_X5R_10V  [C0805]  184.44 15.96 90 top
CA6  100nF_X5R_10V  [C0402]  182.02 19.89 180 top
CA7  10uF_X5R_6.3V  [C0603]  179.74 15.19 180 top
CA8  10uF_X5R_6.3V  [C0805]  198.66 26.62 90 top
CA9  100nF_X7R_10V  [C0402]  197.26 25.99 270 top
CA10  10uF_X5R_6.3V  [C0805]  195.11 27.89 0 top
CA11  100nF_X7R_10V  [C0402]  191.09 23.42 180 top
CA12  10uF_X5R_6.3V  [C0603]  179.1 23.19 180 top
CA15  10uF_X5R_6.3V  [C0805]  195.11 26.12 0 top
CA16  100nF_X7R_10V  [C0402]  190.66 27.39 180 top
CA17  100nF_X7R_16V  [C0402]  178.47 30.94 90 top
CA18  10uF_X5R_6.3V  [C0805]  184.31 30.31 270 top
CA19  1uF_X5R_16V  [C0402]  177.45 35.01 90 top
CA20  1uF_X5R_16V  [C0402]  176.44 35.01 90 top
CA21  10uF_X5R_6.3V  [C0603]  188.63 29.54 180 top
CA22  100nF_X7R_10V  [C0402]  188.25 28.4 0 top
CA23  100nF_X7R_16V  [C0402]  188.25 32.97 0 top
CA24  12pF_NPO_50V  [C0402]  180.5 30.94 90 top
CA25  22pF_NPO_25V  [C0402]  179.48 30.94 90 top
CA27  100nF_X7R_10V  [C0402]  182.79 30.94 270 top
CA28  10uF_X5R_6.3V  [C0603]  181.64 30.81 90 top
CA29  22pF_NPO_25V  [C0402]  185.71 30.05 90 top
CA74  10nF_X7R_25V  [C0402]  194.72 16.08 315 top
CA75  10nF_X7R_25V  [C0402]  175.8 28.91 90 top
CA76  10nF_X7R_25V  [C0402]  222.54 13.16 90 top
CA77  10nF_X7R_25V  [C0402]  192.65 10.67 0 top
CA78  470pF_X7R_50V  [C0402]  235.36 242.95 0 top
CA79  1nF_X7R_50V  [C0402]  192.69 24.46 90 top
CA80  470pF_X7R_50V  [C0402]  235.36 244.47 0 top
CA82  1nF_X7R_50V  [C0402]  192.57 26.5 90 top
CA83  22uF_X5R_16V  [C1206_H73]  179.74 19 270 top
CA84  100pF_NPO_50V  [C0402]  165.29 48.16 180 top
CA85  22uF_X5R_16V  [C1206_H73]  177.58 19 270 top
CA86  1uF_X5R_10V  [C0603]  191.17 25.48 90 top
CA87  100pF_NPO_50V  [C0402]  163.25 48.16 180 top
CA88  2.2uF_X5R_6.3V  [C0805_H53]  199.17 18.11 270 top
CA89  10uF_X5R_6.3V  [C0805]  206.79 55.25 270 top
CA90  1uF_X5R_6.3V  [C0402]  189.36 17.58 180 top
CA91  1uF_X5R_6.3V  [C0402]  189.52 18.75 180 top
CA92  100pF_NPO_50V  [C0402]  177.45 30.94 270 top
CA101  1nF_X7R_16V  [C0402]  201.07 19.26 0 top
CA102  100nF_X7R_10V  [C0402]  191.55 22.05 0 top
CA103  100nF_X7R_10V  [C0402]  174.15 22.18 180 top
CA104  100nF_X7R_10V  [C0402]  178.09 26.37 0 top
CA105  100nF_X7R_10V  [C0402]  180.12 26.37 0 top
CA106  100nF_X7R_10V  [C0402]  171.74 21.16 180 top
CA107  10nF_X7R_25V  [C0402]  226.35 254.25 180 top
CA108  10nF_X7R_25V  [C0402]  232.57 241.17 180 top
CA109  10nF_X7R_25V  [C0402]  231.94 235.08 180 top
CA110  10nF_X7R_25V  [C0402]  208.44 15.32 90 top
CA111  1nF_X7R_50V  [C0402]  161.96 50.8 180 top
CA116  100nF_X7R_16V  [C0402]  232.95 237.87 180 top
CA117  100nF_X7R_16V  [C0402]  234.48 240.03 90 top
CA118  680pF_X7R_50V  [C0402]  176.18 6.56 180 top
CA119  680pF_X7R_50V  [C0402]  189.01 6.56 0 top
CA120  100pF_NPO_16V  [C0402]  188.25 13.16 90 top
CA121  100pF_NPO_16V  [C0402]  189.64 13.16 90 top
CA122  10uF_X5R_10V  [C0805]  174.02 20.02 270 top
CA123  10uF_X5R_10V  [C0805]  175.67 20.02 270 top
CA124  10nF_X7R_25V  [C0402]  238.92 110.49 180 top
CA125  10nF_X7R_25V  [C0402]  238.92 62.99 180 top
CA126  10nF_X7R_25V  [C0402]  238.92 41.53 180 top
CB1  22pF_NPO_50V  [C0402]  13.5 158.12 0 top
CB2  10nF_X7R_25V  [C0402]  13.5 153.03 0 top
CB3  100nF_X7R_16V  [C0402]  13.5 149.99 0 top
CB4  100nF_X7R_16V  [C0402]  13.5 154.94 0 top
CB5  470pF_X7R_50V  [C0402]  8.67 118.36 180 top
CD1  100nF_X7R_16V  [C0402]  148.75 75.31 90 top
CD2  2.2uF_X5R_6.3V  [C0402]  223.05 84.51 270 top
CD3  100nF_X7R_16V  [C0402]  222.08 84.51 270 top
CD4  100nF_X7R_10V  [C0402]  215.04 75.44 270 top
CD5  4.7uF_X5R_6.3V  [C0603]  224.95 84.84 0 top
CD6  22nF_X7R_16V  [C0402]  228.02 84.53 90 top
CF1  100nF_X7R_16V  [C0402]  237.78 135.51 180 top
CF2  100nF_X7R_16V  [C0402]  235.24 135.76 90 top
CF3  120uF_EC_16V  [CE25D63H125]  229.04 124.84 0 top
CF4  47nF_X7R_25V  [C0603]  203.23 223.52 0 top
CF5  100nF_X7R_16V  [C0402]  199.42 231.52 180 top
CF6  1uF_X5R_10V  [C0603]  222.79 230.38 90 top
CF7  100nF_X7R_16V  [C0402]  218.73 228.6 270 top
CF8  1uF_X5R_6.3V  [C0402]  33.56 103.38 270 top
CF9  100nF_X7R_10V  [C0402]  32.55 103.38 270 top
CF10  100nF_X7R_10V  [C0402]  31.53 103.38 270 top
CF11  10uF_X5R_6.3V  [C0603]  39.66 97.79 270 top
CF12  100nF_X7R_10V  [C0402]  36.86 90.42 180 top
CF13  10uF_X5R_6.3V  [C0603]  39.66 100.58 90 top
CF14  10uF_X5R_16V  [C1206_H53]  203.11 232.03 180 top
CF18  100nF_X7R_10V  [C0402]  35.72 100.97 90 top
CF19  100nF_X7R_10V  [C0402]  36.86 100.97 270 top
CF20  100nF_X7R_10V  [C0402]  30.01 90.3 0 top
CF21  100nF_X7R_10V  [C0402]  36.86 89.41 180 top
CF22  100nF_X7R_10V  [C0402]  36.86 98.93 270 top
CF23  100nF_X7R_10V  [C0402]  30.01 92.58 180 top
CF24  100nF_X7R_10V  [C0402]  34.58 98.93 270 top
CF103  100nF_X7R_10V  [C0402]  18.32 157.73 270 top
CF104  100nF_X7R_10V  [C0402]  21.5 152.27 180 top
CF105  10uF_X5R_6.3V  [C0603]  25.81 152.27 270 top
CF106  100nF_X7R_10V  [C0402]  25.94 154.69 90 top
CF107  100nF_X7R_10V  [C0402]  18.96 149.73 180 top
CF108  10pF_NPO_25V  [C0402]  18.96 145.16 180 top
CF109  10pF_NPO_25V  [C0402]  25.05 149.73 0 top
CF110  120uF_EC_16V  [CE25D63H125]  209.84 232.41 0 top
CG1  100nF_X7R_16V  [C0402]  143.05 227.84 0 top
CG2  100nF_X7R_16V  [C0402]  143.05 226.82 0 top
CG3  100nF_X7R_16V  [C0402]  143.05 224.03 0 top
CG4  100nF_X7R_16V  [C0402]  143.05 223.01 0 top
CG5  100nF_X7R_16V  [C0402]  143.56 222 0 top
CG6  100nF_X7R_16V  [C0402]  143.56 220.98 0 top
CG7  2pF_NPO_50V  [C0402]  169.09 233.81 180 top
CG8  2pF_NPO_50V  [C0402]  168.7 236.09 180 top
CG9  2pF_NPO_50V  [C0402]  166.29 233.81 180 top
CG10  2pF_NPO_50V  [C0402]  165.91 236.09 180 top
CG11  2pF_NPO_50V  [C0402]  163.5 233.81 180 top
CG12  2pF_NPO_50V  [C0402]  163.12 236.09 180 top
CG13  10pF_NPO_50V  [C0402]  171.12 236.09 180 top
CG14  10pF_NPO_50V  [C0402]  173.66 236.09 180 top
CG15  100nF_X7R_16V  [C0402]  203.19 251.33 180 top
CG16  100pF_NPO_16V  [C0402]  191.35 234.06 0 top
CG17  100nF_X7R_10V  [C0402]  170.48 226.31 180 top
CG18  100nF_X7R_10V  [C0402]  157.39 235.08 270 top
CG19  100nF_X7R_16V  [C0402]  153.21 220.22 180 top
CG20  100nF_X7R_16V  [C0402]  155.75 222.76 180 top
CG21  10uF_X5R_6.3V  [C0805]  155.75 221.36 0 top
CG22  100nF_X7R_16V  [C0402]  145.84 227.58 0 top
CG23  10uF_X5R_6.3V  [C0805]  144.31 230.25 180 top
CG24  100nF_X7R_16V  [C0402]  145.07 228.85 0 top
CG25  100nF_X7R_16V  [C0402]  150.78 232.03 180 top
CG26  100nF_X7R_16V  [C0402]  152.31 229.62 0 top
CG27  2.2uF_X5R_6.3V  [C0603_H35]  151.93 230.89 180 top
CK1  100nF_X7R_16V  [C0402]  50.71 193.04 180 top
CK2  100nF_X7R_16V  [C0402]  50.71 196.98 180 top
CK3  1nF_X7R_50V  [C0402]  52.1 188.09 0 top
CK4  1nF_X7R_50V  [C0402]  50.71 192.15 180 top
CK5  100nF_X7R_50V  [C0805]  65.95 184.53 180 top
CK6  100nF_X7R_16V  [C0402]  50.71 193.93 180 top
CK7  100nF_X7R_50V  [C0805]  64.3 206.38 90 top
CK8  1uF_X5R_6.3V  [C0402]  51.21 200.03 90 top
CK9  100nF_X7R_16V  [C0402]  32.76 193.52 270 top
CK10  10nF_X7R_16V  [C0402]  50.2 200.03 90 top
CK11  1nF_X7R_50V  [C0402]  49.18 200.03 90 top
CK12  100nF_X7R_16V  [C0402]  68.61 199.39 0 top
CK13  1uF_X5R_6.3V  [C0402]  52.87 207.31 180 top
CK14  10nF_X7R_16V  [C0402]  52.87 208.33 180 top
CK15  1nF_X7R_50V  [C0402]  52.87 206.3 180 top
CK16  1uF_X5R_6.3V  [C0402]  50.96 204.72 90 top
CK19  10nF_X7R_16V  [C0402]  49.94 204.72 90 top
CK20  1nF_X7R_50V  [C0402]  48.93 204.72 90 top
CK23  1nF_X7R_50V  [C0402]  60.74 208.53 270 top
CK25  100nF_X7R_16V  [C0402]  55.41 236.09 270 top
CK26  100nF_X7R_16V  [C0402]  46.77 216.41 270 top
CK27  100nF_X7R_16V  [C0402]  26.7 167 0 top
CK28  100nF_X7R_16V  [C0402]  34.91 212.22 180 top
CK29  100nF_X7R_16V  [C0402]  34.83 202.69 180 top
CK30  100nF_X7R_16V  [C0402]  35.72 164.85 270 top
CK31  100nF_X7R_16V  [C0402]  26.7 168.02 0 top
CK32  100nF_X7R_16V  [C0402]  75.6 227.58 180 top
CK33  100nF_X7R_16V  [C0402]  47.02 167.64 0 top
CK34  100nF_X7R_16V  [C0402]  35.72 244.98 90 top
CK35  100nF_X7R_16V  [C0402]  50.71 197.87 180 top
CK36  100nF_X7R_16V  [C0402]  52.1 187.07 0 top
CK37  100nF_X7R_16V  [C0402]  52.1 186.06 0 top
CK38  100nF_X7R_16V  [C0402]  54.39 208.34 270 top
CK39  100nF_X7R_16V  [C0402]  60.61 183.13 270 top
CK40  100nF_X7R_16V  [C0402]  65.95 186.06 180 top
CK41  100nF_X7R_16V  [C0402]  68.61 196.6 0 top
CK42  100nF_X7R_16V  [C0402]  62.77 205.74 90 top
CK43  100nF_X7R_16V  [C0402]  34.83 204.6 180 top
CK44  100nF_X7R_16V  [C0402]  70.14 187.71 90 top
CK45  100nF_X7R_16V  [C0402]  59.09 181.99 0 top
CK46  100nF_X7R_16V  [C0402]  57.06 182.5 180 top
CK47  100nF_X7R_16V  [C0402]  68.61 200.28 0 top
CK48  100nF_X7R_16V  [C0402]  67.85 179.7 0 top
CK49  100nF_X7R_16V  [C0402]  54.26 184.02 270 top
CK50  100nF_X7R_16V  [C0402]  68.61 197.49 0 top
CK51  100nF_X7R_16V  [C0402]  68.61 198.37 0 top
CK52  1nF_X7R_50V  [C0402]  55.28 184.02 270 top
CK53  100nF_X7R_16V  [C0402]  69.25 190.75 0 top
CK54  100nF_X7R_16V  [C0402]  65.69 205.74 90 top
CK56  2.2uF_X5R_6.3V  [C0805_H53]  65.18 180.34 180 top
CK58  10uF_X5R_6.3V  [C0805]  65.95 187.45 180 top
CK59  100nF_X7R_16V  [C0402]  26.82 237.82 0 top
CK60  100nF_X7R_16V  [C0402]  27.59 222.88 0 top
CK61  100nF_X7R_16V  [C0402]  26.7 169.04 0 top
CK62  100nF_X7R_16V  [C0402]  26.2 245.87 90 top
CK63  100nF_X7R_16V  [C0402]  26.7 202.06 0 top
CK64  100nF_X7R_16V  [C0402]  13.24 238.12 90 top
CK65  100nF_X7R_16V  [C0402]  27.02 209.93 0 top
CK66  100nF_X7R_16V  [C0402]  26.83 225.93 270 top
CK67  100nF_X7R_16V  [C0402]  27.59 223.9 0 top
CK68  100nF_X7R_16V  [C0402]  26.61 217.53 0 top
CL1  100nF_X7R_16V  [C0402]  107.35 223.27 0 top
CL2  100nF_X7R_16V  [C0402]  107.35 224.28 0 top
CL3  100nF_X7R_16V  [C0402]  73.19 127.51 90 top
CL4  100nF_X7R_16V  [C0402]  72.17 127.51 90 top
CL5  4.7uF_X5R_10V  [C0805]  117 230.25 0 top
CL6  100nF_X7R_16V  [C0402]  114.84 230.25 90 top
CL15  100nF_X7R_16V  [C0402]  106.08 229.49 90 top
CL17  4.7uF_X5R_10V  [C0805]  104.68 230 90 top
CL23  100nF_X7R_16V  [C0402]  102.35 236.69 270 top
CL31  470pF_X7R_50V  [C0402]  117.76 223.77 0 top
CL32  470pF_X7R_50V  [C0402]  117.76 224.79 0 top
CL33  470pF_X7R_50V  [C0402]  101.89 234.06 180 top
CL34  470pF_X7R_50V  [C0402]  117.76 225.81 180 top
CL35  27pF_NPO_50V  [C0402]  118.65 227.84 0 top
CL36  27pF_NPO_50V  [C0402]  118.65 226.82 0 top
CL41  100nF_X7R_16V  [C0402]  113.57 224.28 90 top
CL42  4.7uF_X5R_10V  [C0805]  109.63 221.36 180 top
CL43  100nF_X5R_16V  [C0402]  114.46 220.47 270 top
CL44  100nF_X7R_16V  [C0402]  109.63 217.93 180 top
CL45  100nF_X7R_16V  [C0402]  115.73 227.84 0 top
CL46  100nF_X7R_16V  [C0402]  113.32 231.39 0 top
CL47  100nF_X7R_16V  [C0402]  107.6 230.63 180 top
CL48  1uF_X5R_6.3V  [C0402]  109.63 218.95 180 top
CL49  100nF_X7R_16V  [C0402]  109.63 219.96 180 top
CL50  4.7uF_X5R_10V  [C0805]  112.68 220.73 90 top
CL51  100nF_X7R_16V  [C0402]  111.92 222.88 0 top
CL52  1uF_X5R_6.3V  [C0402]  56.68 250.19 0 top
CL53  1uF_X5R_6.3V  [C0402]  62.01 250.19 0 top
CL54  1uF_X5R_6.3V  [C0402]  64.3 250.19 180 top
CL55  1uF_X5R_6.3V  [C0402]  69.12 250.19 0 top
CL56  1uF_X5R_6.3V  [C0402]  66.96 251.21 270 top
CL57  2.2uF_X5R_10V  [C0603]  65.82 251.71 270 top
CL58  1uF_X5R_6.3V  [C0402]  72.04 252.73 270 top
CL59  2.2uF_X5R_10V  [C0603]  73.19 252.98 270 top
CM1  10nF_X7R_16V  [C0402]  102.14 121.28 270 top
CM2  10nF_X7R_16V  [C0402]  103.16 121.28 270 top
CM3  10nF_X7R_16V  [C0402]  104.17 121.28 270 top
CM4  10nF_X7R_16V  [C0402]  105.19 121.28 270 top
CM5  100nF_X7R_10V  [C0402]  103.41 134.37 180 top
CM6  10uF_X5R_6.3V  [C0603]  104.43 132.33 180 top
CNO1  180pF_NPO_50V  [8P4C0603]  177.2 231.65 270 top
CNO2  180pF_NPO_50V  [8P4C0603]  177.2 227.84 270 top
CO1  100nF_X7R_10V  [C0402]  217.46 35.05 0 top
CO2  100nF_X7R_10V  [C0402]  225.33 33.66 90 top
CO3  100nF_X7R_10V  [C0402]  210.98 35.05 0 top
CO4  100nF_X7R_10V  [C0402]  206.92 47.62 270 top
CO5  100nF_X7R_10V  [C0402]  224.44 53.47 270 top
CO6  100nF_X7R_10V  [C0402]  226.98 51.18 180 top
CO7  100nF_X7R_10V  [C0402]  218.98 54.99 270 top
CO8  100nF_X7R_10V  [C0402]  226.98 47.62 180 top
CO9  100nF_X7R_10V  [C0402]  226.98 43.18 180 top
CO10  100nF_X7R_10V  [C0402]  220.89 33.66 90 top
CO11  1uF_X5R_6.3V  [C0603]  215.93 32.26 180 top
CO12  100nF_X7R_10V  [C0402]  223.3 33.66 90 top
CO13  100nF_X7R_10V  [C0402]  205.65 42.16 0 top
CO14  100pF_NPO_50V  [C0402]  224.32 33.66 270 top
CO16  2.2nF_X7R_16V  [C0603]  226.98 40.13 0 top
CO17  2.2nF_X7R_16V  [C0603]  228.13 41.91 0 top
CO18  4.7uF_X5R_10V  [C0603]  209.33 35.94 270 top
CO19  1uF_X5R_6.3V  [C0402]  205.65 41.15 180 top
CO20  2.2uF_X5R_10V  [C0603]  205.65 40 180 top
CO25  100nF_X7R_16V  [C0402]  138.67 235.33 90 top
CO26  100nF_X7R_16V  [C0402]  137.65 235.33 90 top
CO27  100nF_X7R_16V  [C0402]  136.64 235.33 90 top
CO28  100nF_X7R_16V  [C0402]  135.62 235.33 90 top
CO32  10nF_X7R_25V  [C0402]  178.47 235.08 180 top
CO33  10nF_X7R_25V  [C0402]  181.9 225.3 0 top
CO42  100nF_X7R_16V  [C0402]  108.87 37.21 90 top
CO43  100nF_X7R_16V  [C0402]  145.59 22.33 90 top
CO44  100nF_X7R_16V  [C0402]  144.57 22.33 90 top
CO45  100nF_X7R_16V  [C0402]  140.51 22.33 90 top
CO46  100nF_X7R_16V  [C0402]  139.37 22.33 90 top
CO51  47pF_NPO_25V  [C0402]  52.36 139.45 90 top
CO52  470pF_X7R_50V  [C0402]  221.21 16.56 270 top
CO53  470pF_X7R_50V  [C0402]  199.55 12.4 180 top
CO54  470pF_X7R_50V  [C0402]  219.68 18.46 180 top
CO55  470pF_X7R_50V  [C0402]  41.82 150.62 180 top
CO56  470pF_X7R_50V  [C0402]  215.87 20.62 270 top
COOLER  COOLER  [CL_LGA1151_PHOENIX]  165.09 146.95 270 top
CPO1  SHORT-PAD-4  [R0402_S4MIL_MVB]  182.41 234.19 0 top
CPO2  SHORT-PAD-4  [R0402_S4MIL_MVB]  178.21 225.43 180 top
CPU  Socket_LGA 1151_15u_Black  [LGA1151]  165.7 146.95 0 top
CPU_2  CPU Loading Moudle_115X  [SK_BP_LGA115X]  161.4 146.95 0 top
CS69  1uF_X5R_6.3V  [C0402]  173.09 32 270 top
CS73  100nF_X7R_16V  [C0402]  115.35 133.73 90 top
CS75  100nF_X7R_16V  [C0402]  115.1 131.57 90 top
CS78  100nF_X7R_16V  [C0402]  120.43 157.99 180 top
CS82  100nF_X7R_16V  [C0402]  120.05 156.84 180 top
CS83  100nF_X7R_16V  [C0402]  125.64 166.37 135 top
CS84  100nF_X7R_16V  [C0402]  130.34 175.01 135 top
CS97  100nF_X7R_16V  [C0402]  65.31 104.9 90 top
CS111  100nF_X7R_16V  [C0402]  60.87 91.19 225 top
CS112  100nF_X7R_16V  [C0402]  114.46 135.89 270 top
CS118  100nF_X7R_16V  [C0402]  69.76 177.93 315 top
CS120  100nF_X7R_16V  [C0402]  70.14 168.53 45 top
CS126  100nF_X7R_16V  [C0402]  9.56 65.53 90 top
CS128  100nF_X7R_16V  [C0402]  90.2 230.12 90 top
CS129  100nF_X7R_16V  [C0402]  48.55 195.58 270 top
CS131  100nF_X7R_16V  [C0402]  65.82 212.85 45 top
CS132  100nF_X7R_16V  [C0402]  101.63 49.4 0 top
CS133  100nF_X7R_16V  [C0402]  33.89 140.82 315 top
CS140  100nF_X7R_16V  [C0402]  113.57 37.72 90 top
CS141  100nF_X7R_16V  [C0402]  114.59 37.72 90 top
CS142  100nF_X7R_16V  [C0402]  152.31 12.02 90 top
CS143  100nF_X7R_16V  [C0402]  228.63 117.35 135 top
CS144  100nF_X7R_16V  [C0402]  230.67 236.6 0 top
CS145  100nF_X7R_16V  [C0402]  238.67 113.54 0 top
CS148  100nF_X7R_16V  [C0402]  129.32 173.99 135 top
CS154  100nF_X7R_16V  [C0402]  85.76 242.44 0 top
CS156  100nF_X7R_16V  [C0402]  234.6 141.35 180 top
CS161  100nF_X7R_16V  [C0402]  70.39 47.75 270 top
CS162  100nF_X7R_16V  [C0402]  33.43 247.65 90 top
CS165  100nF_X7R_16V  [C0402]  235.8 69.9 270 top
CS166  100nF_X7R_16V  [C0402]  107.73 37.21 90 top
CS171  100nF_X7R_16V  [C0402]  89.7 139.19 90 top
CS175  100nF_X7R_16V  [C0402]  41.05 151.89 315 top
CS176  100nF_X7R_16V  [C0402]  51.09 232.03 135 top
CS177  100nF_X7R_16V  [C0402]  31.78 160.27 0 top
CS178  100nF_X7R_16V  [C0402]  18.07 33.53 90 top
CS179  100nF_X7R_16V  [C0402]  43.59 35.18 180 top
CS180  100nF_X7R_16V  [C0402]  22.51 132.97 0 top
CS181  100nF_X7R_16V  [C0402]  17.56 134.11 180 top
CS182  100nF_X7R_16V  [C0402]  32.34 143.59 90 top
CS183  100nF_X7R_16V  [C0402]  26.45 144.27 225 top
CS184  100nF_X7R_16V  [C0402]  23.15 144.4 270 top
CS185  100nF_X7R_16V  [C0402]  27.97 147.07 270 top
CS186  100nF_X7R_16V  [C0402]  17.56 146.41 270 top
CS187  100nF_X7R_16V  [C0402]  17.03 149.61 90 top
CS188  100nF_X7R_16V  [C0402]  18.32 123.37 90 top
CS189  100nF_X7R_16V  [C0402]  38.64 59.18 225 top
CS190  100nF_X7R_16V  [C0402]  54.26 85.34 270 top
CS191  100nF_X7R_16V  [C0402]  56.68 81.15 270 top
CS192  100nF_X7R_16V  [C0402]  45.88 83.31 225 top
CS193  100nF_X7R_16V  [C0402]  26.32 85.22 0 top
CS194  100nF_X7R_16V  [C0402]  28.74 76.58 0 top
CS195  100nF_X7R_16V  [C0402]  25.81 79.12 180 top
CS196  100nF_X7R_16V  [C0402]  18.07 81.15 180 top
CS197  100nF_X7R_16V  [C0402]  15.91 69.98 180 top
CS198  100nF_X7R_16V  [C0402]  51.9 224.84 270 top
CS199  100nF_X7R_16V  [C0402]  47.33 195.6 270 top
CS200  100nF_X7R_16V  [C0402]  66.99 170.26 180 top
CS201  100nF_X7R_16V  [C0402]  68.61 233.81 45 top
CS202  100nF_X7R_16V  [C0402]  54.26 232.28 90 top
CS203  100nF_X7R_16V  [C0402]  48.5 225.85 270 top
CS204  100nF_X7R_16V  [C0402]  28.31 153.18 90 top
CS205  100nF_X7R_16V  [C0402]  34.97 172.87 135 top
CS206  100nF_X7R_16V  [C0402]  38.03 158.75 0 top
CS207  100nF_X7R_16V  [C0402]  31.4 155.07 90 top
CS208  100nF_X7R_16V  [C0402]  131.61 173.35 0 top
CS209  100nF_X7R_16V  [C0402]  128.94 165.74 0 top
CS210  100nF_X7R_16V  [C0402]  128.99 160.25 180 top
CS211  100nF_X7R_16V  [C0402]  124.75 154.94 45 top
CS212  100nF_X7R_16V  [C0402]  133.13 33.53 45 top
CS213  100nF_X7R_16V  [C0402]  147.23 62.74 0 top
CS214  100nF_X7R_16V  [C0402]  5.37 209.55 270 top
CS215  100nF_X7R_16V  [C0402]  11.97 36.07 180 top
CS216  100nF_X7R_16V  [C0402]  18.07 35.56 90 top
CS217  100nF_X7R_16V  [C0402]  94.52 116.08 0 top
CS218  100nF_X7R_16V  [C0402]  118.52 139.29 0 top
CSA1  10nF_X7R_25V  [C0402]  123.35 64.13 0 top
CSA2  10nF_X7R_25V  [C0402]  123.35 65.15 0 top
CSA3  10nF_X7R_25V  [C0402]  119.41 64.13 0 top
CSA4  10nF_X7R_25V  [C0402]  119.41 65.15 0 top
CSA5  10nF_X7R_25V  [C0402]  142.67 63.33 270 top
CSA6  10nF_X7R_25V  [C0402]  141.65 63.33 270 top
CSA7  10nF_X7R_25V  [C0402]  140.64 63.33 270 top
CSA8  10nF_X7R_25V  [C0402]  139.62 63.33 270 top
CSA9  10nF_X7R_25V  [C0402]  137.95 64.67 90 top
CSA10  10nF_X7R_25V  [C0402]  136.94 64.67 90 top
CSA11  10nF_X7R_25V  [C0402]  135.92 64.67 90 top
CSA12  10nF_X7R_25V  [C0402]  134.91 64.67 90 top
CU2  100nF_X7R_16V  [C0402]  143.92 248.16 90 top
CU3  100nF_X7R_16V  [C0402]  131.22 229.87 180 top
CU5  100nF_X7R_16V  [C0402]  93.63 253.62 90 top
CU10  100nF_X7R_16V  [C0402]  131.86 8.59 270 top
CU11  100nF_X7R_16V  [C0402]  132.88 8.59 270 top
CU13  100nF_X7R_16V  [C0402]  55.41 76.2 180 top
CU14  100nF_X7R_16V  [C0402]  54.64 73.66 90 top
CU79  100nF_X7R_16V  [C0402]  155.74 12.02 270 top
CV32  100nF_X7R_16V  [C0402]  205.61 242.98 90 top
CV33  100nF_X7R_16V  [C0402]  206.62 242.98 90 top
CV34  100nF_X7R_16V  [C0402]  208.66 242.98 90 top
CV35  100nF_X7R_16V  [C0402]  209.67 242.98 90 top
CV36  100nF_X7R_16V  [C0402]  211.7 242.98 90 top
CV37  100nF_X7R_16V  [C0402]  212.72 242.98 90 top
CV38  100nF_X7R_16V  [C0402]  214.75 242.98 90 top
CV39  100nF_X7R_16V  [C0402]  215.77 242.98 90 top
CV40  100nF_X7R_16V  [C0402]  225.54 241.3 270 top
CV41  100nF_X7R_16V  [C0402]  222.62 246.38 0 top
CV42  470pF_X7R_50V  [C0402]  222.54 242.06 270 top
CX1  100nF_X7R_16V  [C0402]  52.23 253.75 90 top
CX14  100nF_X7R_16V  [C0402]  75.6 232.66 180 top
CX15  220nF_X5R_10V  [C0402]  87.66 221.84 135 top
CX16  220nF_X5R_10V  [C0402]  88.38 222.56 135 top
CX17  220nF_X5R_10V  [C0402]  87.51 217.62 180 top
CX18  100nF_X7R_16V  [C0402]  76.11 236.85 270 top
CX19  100nF_X7R_16V  [C0402]  66.45 237.11 270 top
CX20  100nF_X7R_16V  [C0402]  89.19 230.63 90 top
CX21  220nF_X5R_10V  [C0402]  87.51 218.74 180 top
CX22  220nF_X5R_10V  [C0402]  87.52 215.44 180 top
CX23  220nF_X5R_10V  [C0402]  87.52 214.3 180 top
CX24  220nF_X5R_10V  [C0402]  87.31 210.18 180 top
CX25  100nF_X7R_16V  [C0402]  66.07 227.33 90 top
CX26  220nF_X5R_10V  [C0402]  87.31 211.2 180 top
CX27  220nF_X5R_10V  [C0402]  87.33 205.33 180 top
CX28  220nF_X5R_10V  [C0402]  87.33 204.32 180 top
CX29  220nF_X5R_10V  [C0402]  87.28 201.3 180 top
CX30  220nF_X5R_10V  [C0402]  87.28 200.28 180 top
CX31  220nF_X5R_10V  [C0402]  87.24 197.33 180 top
CX32  220nF_X5R_10V  [C0402]  87.24 196.32 180 top
CX33  220nF_X5R_10V  [C0402]  87.26 193.32 180 top
CX34  220nF_X5R_10V  [C0402]  87.26 192.3 180 top
CX35  220nF_X5R_10V  [C0402]  87.26 187.35 180 top
CX36  220nF_X5R_10V  [C0402]  87.26 186.34 180 top
CX37  220nF_X5R_10V  [C0402]  87.24 183.23 180 top
CX38  220nF_X5R_10V  [C0402]  87.24 182.22 180 top
CX39  220nF_X5R_10V  [C0402]  87.24 179.3 180 top
CX41  220nF_X5R_10V  [C0402]  87.24 175.36 180 top
CX42  220nF_X5R_10V  [C0402]  87.24 174.34 180 top
CX43  220nF_X5R_10V  [C0402]  87.37 171.3 180 top
CX44  220nF_X5R_10V  [C0402]  87.37 170.28 180 top
CX45  220nF_X5R_10V  [C0402]  87.24 167.36 180 top
CX46  220nF_X5R_10V  [C0402]  87.24 166.34 180 top
CX47  220nF_X5R_10V  [C0402]  87.5 163.68 180 top
CX52  100nF_X5R_10V  [C0402]  54.39 221.74 90 top
CX53  100nF_X5R_10V  [C0402]  55.41 221.74 90 top
CX54  1nF_X7R_50V  [C0402]  66.58 228.85 0 top
CX55  100nF_X7R_16V  [C0402]  66.58 230.12 0 top
CX56  100nF_X7R_16V  [C0402]  55.41 232.28 90 top
CX57  100nF_X7R_16V  [C0402]  55.41 229.36 90 top
CX83  100nF_X7R_16V  [C0402]  86.39 234.95 270 top
CX84  100nF_X7R_16V  [C0402]  35.85 240.79 270 top
CX98  220nF_X5R_10V  [C0402]  87.24 178.28 180 top
CX99  220nF_X5R_10V  [C0402]  87.5 162.66 180 top
CX100  220nF_X5R_10V  [C0402]  87.54 159.84 180 top
CX101  220nF_X5R_10V  [C0402]  87.54 158.83 180 top
CX118  100nF_X5R_10V  [C0402]  51.09 189.87 90 top
CX119  100nF_X5R_10V  [C0402]  50.07 189.87 90 top
CX126  100nF_X5R_10V  [C0402]  50.71 194.94 0 top
CX127  100nF_X5R_10V  [C0402]  50.71 195.96 0 top
D1  BAT54C-7-F_200mA  [SOT23_123]  171.1 51.44 180 top
D5  BAT54C-7-F_200mA  [SOT23_123]  171.1 48.01 180 top
